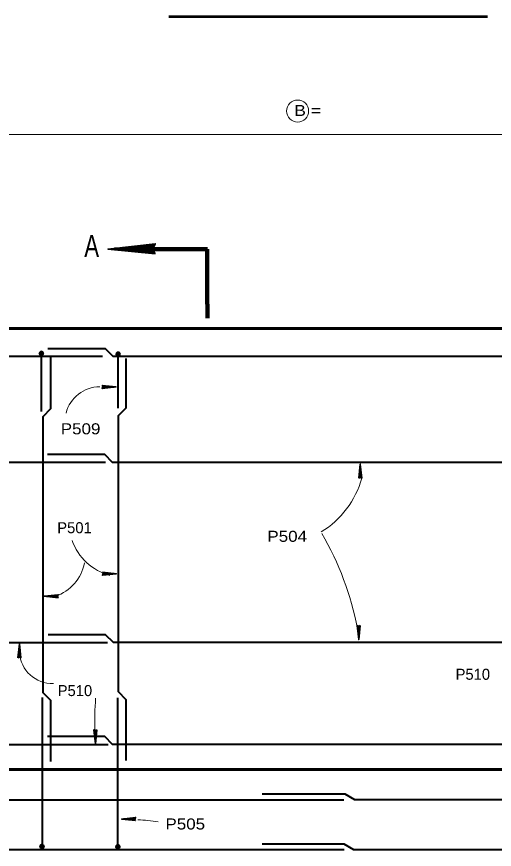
# Model space of a CAD drawing. Extents: x 14.14 to 17.34, y -1.61 to 0.38.
# Drawn here: x 14.587 to 14.948, y -1.265 to -0.636 of the extents above; entities that cross this region are included whole.
import ezdxf

# ---------------------------------------------------------------- set-up
doc = ezdxf.new("R2010")
doc.units = 0
doc.header["$LTSCALE"] = 0.0033
doc.layers.add('1', color=7, linetype='Continuous', lineweight=40)

msp = doc.modelspace()

# ---------------------------------------------------------------- linework, layer by layer
at = {"layer": '1', "lineweight": 53}
msp.add_line((14.701917, -0.636083), (14.942667, -0.636083), dxfattribs=at)
at = {"layer": '1', "lineweight": 13}
msp.add_line((14.529417, -0.725083), (15.111917, -0.725083), dxfattribs=at)
at = {"layer": '1', "lineweight": 35}
for p, q in [((14.691583, -0.81175), (14.655917, -0.81175)), ((14.690833, -0.8145), (14.66425, -0.811167)), ((14.690833, -0.8145), (14.66425, -0.81175)), ((14.690833, -0.808), (14.666083, -0.81075)), ((14.690833, -0.8085), (14.666083, -0.811167)), ((14.690833, -0.808917), (14.666083, -0.81175)), ((14.691083, -0.8095), (14.666167, -0.811917)), ((14.690833, -0.815167), (14.66425, -0.811917)), ((14.690833, -0.815167), (14.66425, -0.811917)), ((14.690833, -0.81475), (14.66425, -0.811917)), ((14.651417, -0.915917), (14.662, -0.915917)), ((14.651583, -0.916583), (14.658917, -0.915833)), ((14.651667, -0.914917), (14.6595, -0.915833)), ((14.651667, -0.914917), (14.6595, -0.915833)), ((14.651667, -0.915), (14.6595, -0.915833)), ((14.651667, -0.915083), (14.6595, -0.915917)), ((14.651667, -0.915083), (14.6595, -0.916083)), ((14.651667, -0.91675), (14.659, -0.915917)), ((14.651667, -0.916833), (14.659, -0.916083)), ((14.651667, -0.917), (14.659, -0.916167)), ((14.8465, -0.984833), (14.8465, -0.97425)), ((14.8455, -0.984583), (14.846417, -0.97675)), ((14.8455, -0.984583), (14.846417, -0.97675)), ((14.845583, -0.984583), (14.846417, -0.97675)), ((14.845667, -0.984583), (14.8465, -0.97675)), ((14.845667, -0.984583), (14.846667, -0.97675)), ((14.847167, -0.984667), (14.846417, -0.977333)), ((14.847333, -0.984583), (14.8465, -0.97725)), ((14.847417, -0.984583), (14.846667, -0.97725)), ((14.847583, -0.984583), (14.84675, -0.97725)), ((14.65175, -1.057083), (14.662333, -1.057083)), ((14.651917, -1.05775), (14.65925, -1.057)), ((14.652, -1.056083), (14.659833, -1.057)), ((14.652, -1.056083), (14.659833, -1.057)), ((14.652, -1.056167), (14.659833, -1.057)), ((14.652, -1.05625), (14.659833, -1.057083)), ((14.652, -1.05625), (14.659833, -1.05725)), ((14.652, -1.057917), (14.659333, -1.057083)), ((14.652, -1.058), (14.659333, -1.05725)), ((14.652, -1.058167), (14.659333, -1.057333)), ((14.618333, -1.074167), (14.60775, -1.074167)), ((14.618083, -1.075), (14.61025, -1.074)), ((14.618083, -1.075), (14.61025, -1.074167)), ((14.618083, -1.075167), (14.61025, -1.07425)), ((14.618083, -1.075167), (14.61025, -1.07425)), ((14.618083, -1.075083), (14.61025, -1.07425)), ((14.618083, -1.073083), (14.61075, -1.073917)), ((14.618083, -1.07325), (14.61075, -1.074)), ((14.618083, -1.073333), (14.61075, -1.074167)), ((14.618167, -1.0735), (14.610833, -1.07425)), ((14.84425, -1.096583), (14.845083, -1.103917)), ((14.844417, -1.096583), (14.845167, -1.103917)), ((14.8445, -1.096583), (14.845333, -1.103917)), ((14.844667, -1.0965), (14.845417, -1.103833)), ((14.846167, -1.096583), (14.845167, -1.104417)), ((14.845333, -1.096333), (14.845333, -1.106917)), ((14.846167, -1.096583), (14.845333, -1.104417)), ((14.846333, -1.096583), (14.845417, -1.104417)), ((14.846333, -1.096583), (14.845417, -1.104417)), ((14.84625, -1.096583), (14.845417, -1.104417)), ((14.588, -1.120417), (14.588917, -1.112583)), ((14.588, -1.120417), (14.588917, -1.112583)), ((14.588083, -1.120417), (14.588917, -1.112583)), ((14.588167, -1.120417), (14.589, -1.112583)), ((14.588167, -1.120417), (14.589167, -1.112583)), ((14.589667, -1.1205), (14.588917, -1.113167)), ((14.589, -1.120667), (14.589, -1.110083)), ((14.589833, -1.120417), (14.589, -1.113083)), ((14.589917, -1.120417), (14.589167, -1.113083)), ((14.590083, -1.120417), (14.58925, -1.113083)), ((14.645333, -1.175333), (14.646167, -1.182667)), ((14.6455, -1.175333), (14.64625, -1.182667)), ((14.645583, -1.175333), (14.646417, -1.182667)), ((14.64575, -1.17525), (14.6465, -1.182583)), ((14.64725, -1.175333), (14.64625, -1.183167)), ((14.646417, -1.175083), (14.646417, -1.185667)), ((14.64725, -1.175333), (14.646417, -1.183167)), ((14.647417, -1.175333), (14.6465, -1.183167)), ((14.647417, -1.175333), (14.6465, -1.183167)), ((14.647333, -1.175333), (14.6465, -1.183167)), ((14.67675, -1.2425), (14.666167, -1.2425)), ((14.6765, -1.243333), (14.668667, -1.242333)), ((14.6765, -1.243333), (14.668667, -1.2425)), ((14.6765, -1.2435), (14.668667, -1.242583)), ((14.6765, -1.2435), (14.668667, -1.242583)), ((14.6765, -1.243417), (14.668667, -1.242583)), ((14.6765, -1.241417), (14.669167, -1.24225)), ((14.6765, -1.241583), (14.669167, -1.242333)), ((14.6765, -1.241667), (14.669167, -1.2425)), ((14.676583, -1.241833), (14.66925, -1.242583))]:
    msp.add_line(p, q, dxfattribs=at)
at = {"layer": '1', "lineweight": 90}
for p, q in [((14.689417, -0.811833), (14.731083, -0.811833)), ((14.730917, -0.81175), (14.730917, -0.853417)), ((14.731083, -0.8535), (14.731083, -0.864))]:
    msp.add_line(p, q, dxfattribs=at)
at = {"layer": '1', "lineweight": 60}
for p, q in [((14.52925, -0.87175), (14.80725, -0.87175)), ((14.7725, -0.87175), (15.112583, -0.87175))]:
    msp.add_line(p, q, dxfattribs=at)
at = {"layer": '1'}
for p, q in [((14.547333, -0.89275), (14.65175, -0.89275)), ((14.604667, -0.891333), (14.605, -0.889417)), ((14.604833, -0.891417), (14.605167, -0.889417)), ((14.604833, -0.890417), (14.606333, -0.8905)), ((14.604833, -0.8905), (14.606333, -0.890583)), ((14.604833, -0.890583), (14.606333, -0.890667)), ((14.604833, -0.890667), (14.606333, -0.89075)), ((14.604833, -0.89075), (14.606333, -0.890833)), ((14.604833, -0.890833), (14.606333, -0.890917)), ((14.604833, -0.890917), (14.606333, -0.891)), ((14.604833, -0.891083), (14.606333, -0.891167)), ((14.604833, -0.891167), (14.606333, -0.89125)), ((14.604833, -0.89125), (14.606333, -0.891333)), ((14.604833, -0.891333), (14.606333, -0.891417)), ((14.604833, -0.891417), (14.606333, -0.8915)), ((14.604917, -0.889333), (14.606417, -0.889417)), ((14.604917, -0.891417), (14.60525, -0.889417)), ((14.604917, -0.8895), (14.606417, -0.889583)), ((14.604917, -0.889583), (14.606417, -0.889667)), ((14.604917, -0.889667), (14.606417, -0.88975)), ((14.604917, -0.88975), (14.606417, -0.889833)), ((14.604917, -0.889833), (14.606417, -0.889917)), ((14.604917, -0.889917), (14.606417, -0.89)), ((14.604917, -0.89), (14.606417, -0.890083)), ((14.604917, -0.89), (14.606417, -0.890083)), ((14.604917, -0.890083), (14.606417, -0.89025)), ((14.604917, -0.89025), (14.606417, -0.890417)), ((14.605, -0.891417), (14.605417, -0.889417)), ((14.605083, -0.891417), (14.6055, -0.889417)), ((14.60525, -0.891417), (14.605583, -0.8895)), ((14.605333, -0.8915), (14.605667, -0.8895)), ((14.605417, -0.8915), (14.605833, -0.8895)), ((14.6055, -0.8915), (14.605917, -0.889583)), ((14.6055, -0.89275), (14.6055, -0.934417)), ((14.605583, -0.8915), (14.606, -0.889583)), ((14.60575, -0.891583), (14.606167, -0.889583)), ((14.606, -0.891583), (14.606333, -0.889583)), ((14.606083, -0.891583), (14.606417, -0.889667)), ((14.606167, -0.891583), (14.6065, -0.889667)), ((14.60625, -0.891667), (14.606583, -0.889667)), ((14.662583, -0.891917), (14.662917, -0.89)), ((14.66275, -0.892), (14.663083, -0.89)), ((14.66275, -0.891), (14.66425, -0.891083)), ((14.66275, -0.891083), (14.66425, -0.891167)), ((14.66275, -0.891167), (14.66425, -0.89125)), ((14.66275, -0.89125), (14.66425, -0.891333)), ((14.66275, -0.891333), (14.66425, -0.891417)), ((14.66275, -0.891417), (14.66425, -0.8915)), ((14.66275, -0.8915), (14.66425, -0.891583)), ((14.66275, -0.891667), (14.66425, -0.89175)), ((14.66275, -0.89175), (14.66425, -0.891833)), ((14.66275, -0.891833), (14.66425, -0.891917)), ((14.66275, -0.891917), (14.66425, -0.892)), ((14.66275, -0.892), (14.66425, -0.892083)), ((14.662833, -0.889917), (14.664333, -0.89)), ((14.662833, -0.892), (14.663167, -0.89)), ((14.662833, -0.890083), (14.664333, -0.890167)), ((14.662833, -0.890167), (14.664333, -0.89025)), ((14.662833, -0.89025), (14.664333, -0.890333)), ((14.662833, -0.890333), (14.664333, -0.890417)), ((14.662833, -0.890417), (14.664333, -0.8905)), ((14.662833, -0.8905), (14.664333, -0.890583)), ((14.662833, -0.890583), (14.664333, -0.890667)), ((14.662833, -0.890583), (14.664333, -0.890667)), ((14.662833, -0.890667), (14.664333, -0.890833)), ((14.662833, -0.890833), (14.664333, -0.891)), ((14.662917, -0.892), (14.663333, -0.89)), ((14.663, -0.892), (14.663417, -0.89)), ((14.663167, -0.892), (14.6635, -0.890083)), ((14.66325, -0.892083), (14.663583, -0.890083)), ((14.663333, -0.892083), (14.66375, -0.890083)), ((14.663333, -0.89125), (14.663333, -0.932)), ((14.663417, -0.892083), (14.663833, -0.890167)), ((14.6635, -0.892083), (14.663917, -0.890167)), ((14.663667, -0.892167), (14.664083, -0.890167)), ((14.663917, -0.892167), (14.66425, -0.890167)), ((14.664, -0.892167), (14.664333, -0.89025)), ((14.664083, -0.892167), (14.664417, -0.89025)), ((14.664167, -0.89225), (14.6645, -0.89025)), ((14.547917, -0.972833), (14.654083, -0.972833)), ((14.548083, -1.109167), (14.655417, -1.109167)), ((14.606083, -1.150583), (14.606083, -1.263583)), ((14.663167, -1.150833), (14.663167, -1.263833)), ((14.549167, -1.186167), (14.656, -1.186167)), ((14.605417, -1.262083), (14.605083, -1.264083)), ((14.6055, -1.262167), (14.605167, -1.264083)), ((14.605583, -1.262167), (14.60525, -1.264083)), ((14.60675, -1.2635), (14.60525, -1.263333)), ((14.60675, -1.263667), (14.60525, -1.2635)), ((14.60675, -1.26375), (14.60525, -1.263667)), ((14.60675, -1.26375), (14.60525, -1.263667)), ((14.60675, -1.263833), (14.60525, -1.26375)), ((14.60675, -1.263917), (14.60525, -1.263833)), ((14.60675, -1.264), (14.60525, -1.263917)), ((14.60675, -1.264083), (14.60525, -1.264)), ((14.60675, -1.264167), (14.60525, -1.264083)), ((14.60675, -1.26425), (14.60525, -1.264167)), ((14.60675, -1.264417), (14.60525, -1.264333)), ((14.605667, -1.262167), (14.605333, -1.264167)), ((14.606833, -1.262333), (14.605333, -1.26225)), ((14.606833, -1.262417), (14.605333, -1.262333)), ((14.606833, -1.2625), (14.605333, -1.262417)), ((14.606833, -1.262583), (14.605333, -1.2625)), ((14.606833, -1.262667), (14.605333, -1.262583)), ((14.606833, -1.262833), (14.605333, -1.26275)), ((14.606833, -1.262917), (14.605333, -1.262833)), ((14.606833, -1.263), (14.605333, -1.262917)), ((14.606833, -1.263083), (14.605333, -1.263)), ((14.606833, -1.263167), (14.605333, -1.263083)), ((14.606833, -1.26325), (14.605333, -1.263167)), ((14.606833, -1.263333), (14.605333, -1.26325)), ((14.605917, -1.262167), (14.6055, -1.264167)), ((14.606083, -1.26225), (14.605667, -1.264167)), ((14.606167, -1.26225), (14.60575, -1.264167)), ((14.60625, -1.26225), (14.605833, -1.26425)), ((14.606333, -1.26225), (14.606, -1.26425)), ((14.606417, -1.262333), (14.606083, -1.26425)), ((14.606583, -1.262333), (14.606167, -1.264333)), ((14.606667, -1.262333), (14.60625, -1.264333)), ((14.60675, -1.262333), (14.606417, -1.264333)), ((14.606833, -1.262333), (14.6065, -1.264333)), ((14.607, -1.262417), (14.606667, -1.264333)), ((14.66275, -1.26225), (14.662417, -1.26425)), ((14.662833, -1.262333), (14.6625, -1.26425)), ((14.662917, -1.262333), (14.662583, -1.26425)), ((14.664083, -1.263667), (14.662583, -1.2635)), ((14.664083, -1.263833), (14.662583, -1.263667)), ((14.664083, -1.263917), (14.662583, -1.263833)), ((14.664083, -1.263917), (14.662583, -1.263833)), ((14.664083, -1.264), (14.662583, -1.263917)), ((14.664083, -1.264083), (14.662583, -1.264)), ((14.664083, -1.264167), (14.662583, -1.264083)), ((14.664083, -1.26425), (14.662583, -1.264167)), ((14.664083, -1.264333), (14.662583, -1.26425)), ((14.664083, -1.264417), (14.662583, -1.264333)), ((14.664083, -1.264583), (14.662583, -1.2645)), ((14.663, -1.262333), (14.662667, -1.264333)), ((14.664167, -1.2625), (14.662667, -1.262417)), ((14.664167, -1.262583), (14.662667, -1.2625)), ((14.664167, -1.262667), (14.662667, -1.262583)), ((14.664167, -1.26275), (14.662667, -1.262667)), ((14.664167, -1.262833), (14.662667, -1.26275)), ((14.664167, -1.263), (14.662667, -1.262917)), ((14.664167, -1.263083), (14.662667, -1.263)), ((14.664167, -1.263167), (14.662667, -1.263083)), ((14.664167, -1.26325), (14.662667, -1.263167)), ((14.664167, -1.263333), (14.662667, -1.26325)), ((14.664167, -1.263417), (14.662667, -1.263333)), ((14.664167, -1.2635), (14.662667, -1.263417)), ((14.66325, -1.262333), (14.662833, -1.264333)), ((14.663417, -1.262417), (14.663, -1.264333)), ((14.6635, -1.262417), (14.663083, -1.264333)), ((14.663583, -1.262417), (14.663167, -1.264417)), ((14.663667, -1.262417), (14.663333, -1.264417)), ((14.66375, -1.2625), (14.663417, -1.264417)), ((14.663917, -1.2625), (14.6635, -1.2645)), ((14.664, -1.2625), (14.663583, -1.2645)), ((14.664083, -1.2625), (14.66375, -1.2645)), ((14.664167, -1.2625), (14.663833, -1.2645)), ((14.664333, -1.262583), (14.664, -1.2645))]:
    msp.add_line(p, q, dxfattribs=at)
at = {"layer": '1', "lineweight": 35}
for points in [[(14.691583, -0.81525), (14.655917, -0.81175), (14.691583, -0.80775), (14.689667, -0.81175)], [(14.689167, -0.811917), (14.673333, -0.81225), (14.673333, -0.811917), (14.676333, -0.811917), (14.689167, -0.81225), (14.678917, -0.8125), (14.689667, -0.812917), (14.681917, -0.813), (14.689667, -0.813417), (14.677833, -0.8125), (14.662, -0.811917), (14.665083, -0.811167), (14.660917, -0.811167), (14.689167, -0.811167), (14.680833, -0.810667), (14.689667, -0.810667), (14.671667, -0.811917), (14.689667, -0.809667)], [(14.651417, -0.914833), (14.662, -0.915917), (14.651417, -0.917083), (14.652, -0.915917)], [(14.652167, -0.915833), (14.656833, -0.91575), (14.656833, -0.915833), (14.655917, -0.915833), (14.652167, -0.91575), (14.655167, -0.915667), (14.652, -0.915583), (14.65425, -0.9155), (14.652, -0.915417), (14.6555, -0.915667), (14.660167, -0.915833), (14.65925, -0.916083), (14.6605, -0.916083), (14.652167, -0.916083), (14.654583, -0.91625), (14.652, -0.91625), (14.657333, -0.915833), (14.652, -0.9165)], [(14.845417, -0.984833), (14.8465, -0.97425), (14.847667, -0.984833), (14.8465, -0.98425)], [(14.846417, -0.984083), (14.846333, -0.979417), (14.846417, -0.979417), (14.846417, -0.980333), (14.846333, -0.984083), (14.84625, -0.981083), (14.846167, -0.98425), (14.846083, -0.982), (14.846, -0.98425), (14.84625, -0.98075), (14.846417, -0.976083), (14.846667, -0.977), (14.846667, -0.97575), (14.846667, -0.984083), (14.846833, -0.981667), (14.846833, -0.98425), (14.846417, -0.978917), (14.847083, -0.98425)], [(14.65175, -1.056), (14.662333, -1.057083), (14.65175, -1.05825), (14.652333, -1.057083)], [(14.6525, -1.057), (14.657167, -1.056917), (14.657167, -1.057), (14.65625, -1.057), (14.6525, -1.056917), (14.6555, -1.056833), (14.652333, -1.05675), (14.654583, -1.056667), (14.652333, -1.056583), (14.655833, -1.056833), (14.6605, -1.057), (14.659583, -1.05725), (14.660833, -1.05725), (14.6525, -1.05725), (14.654917, -1.057417), (14.652333, -1.057417), (14.657667, -1.057), (14.652333, -1.057667)], [(14.618333, -1.07525), (14.60775, -1.074167), (14.618333, -1.073), (14.61775, -1.074167)], [(14.617583, -1.07425), (14.612917, -1.074333), (14.612917, -1.07425), (14.613833, -1.07425), (14.617583, -1.074333), (14.614583, -1.074417), (14.61775, -1.0745), (14.6155, -1.074583), (14.61775, -1.074667), (14.61425, -1.074417), (14.609583, -1.07425), (14.6105, -1.074), (14.60925, -1.074), (14.617583, -1.074), (14.615167, -1.073833), (14.61775, -1.073833), (14.612417, -1.07425), (14.61775, -1.073583)], [(14.846417, -1.096333), (14.845333, -1.106917), (14.844167, -1.096333), (14.845333, -1.096917)], [(14.845417, -1.097083), (14.8455, -1.10175), (14.845417, -1.10175), (14.845417, -1.100833), (14.8455, -1.097083), (14.845583, -1.100083), (14.845667, -1.096917), (14.84575, -1.099167), (14.845833, -1.096917), (14.845583, -1.100417), (14.845417, -1.105083), (14.845167, -1.104167), (14.845167, -1.105417), (14.845167, -1.097083), (14.845, -1.0995), (14.845, -1.096917), (14.845417, -1.10225), (14.84475, -1.096917)], [(14.587917, -1.120667), (14.589, -1.110083), (14.590167, -1.120667), (14.589, -1.120083)], [(14.588917, -1.119917), (14.588833, -1.11525), (14.588917, -1.11525), (14.588917, -1.116167), (14.588833, -1.119917), (14.58875, -1.116917), (14.588667, -1.120083), (14.588583, -1.117833), (14.5885, -1.120083), (14.58875, -1.116583), (14.588917, -1.111917), (14.589167, -1.112833), (14.589167, -1.111583), (14.589167, -1.119917), (14.589333, -1.1175), (14.589333, -1.120083), (14.588917, -1.11475), (14.589583, -1.120083)], [(14.6475, -1.175083), (14.646417, -1.185667), (14.64525, -1.175083), (14.646417, -1.175667)], [(14.6465, -1.175833), (14.646583, -1.1805), (14.6465, -1.1805), (14.6465, -1.179583), (14.646583, -1.175833), (14.646667, -1.178833), (14.64675, -1.175667), (14.646833, -1.177917), (14.646917, -1.175667), (14.646667, -1.179167), (14.6465, -1.183833), (14.64625, -1.182917), (14.64625, -1.184167), (14.64625, -1.175833), (14.646083, -1.17825), (14.646083, -1.175667), (14.6465, -1.181), (14.645833, -1.175667)], [(14.67675, -1.243583), (14.666167, -1.2425), (14.67675, -1.241333), (14.676167, -1.2425)], [(14.676, -1.242583), (14.671333, -1.242667), (14.671333, -1.242583), (14.67225, -1.242583), (14.676, -1.242667), (14.673, -1.24275), (14.676167, -1.242833), (14.673917, -1.242917), (14.676167, -1.243), (14.672667, -1.24275), (14.668, -1.242583), (14.668917, -1.242333), (14.667667, -1.242333), (14.676, -1.242333), (14.673583, -1.242167), (14.676167, -1.242167), (14.670833, -1.242583), (14.676167, -1.241917)]]:
    msp.add_lwpolyline(points, close=True, dxfattribs=at)
for points in [[(14.689167, -0.811917), (14.690417, -0.8145), (14.689667, -0.813667), (14.689167, -0.8125), (14.688167, -0.812917), (14.688833, -0.814), (14.689333, -0.811417), (14.689917, -0.809667), (14.690833, -0.808417)], [(14.652167, -0.915833), (14.65175, -0.915083), (14.652, -0.915333), (14.652167, -0.915667), (14.652417, -0.915583), (14.65225, -0.91525), (14.652083, -0.916), (14.651917, -0.9165), (14.651667, -0.916917)], [(14.846417, -0.984083), (14.845667, -0.9845), (14.845917, -0.98425), (14.84625, -0.984083), (14.846167, -0.983833), (14.845833, -0.984), (14.846583, -0.984167), (14.847083, -0.984333), (14.8475, -0.984583)], [(14.6525, -1.057), (14.652083, -1.05625), (14.652333, -1.0565), (14.6525, -1.056833), (14.65275, -1.05675), (14.652583, -1.056417), (14.652417, -1.057167), (14.65225, -1.057667), (14.652, -1.058083)], [(14.617583, -1.07425), (14.618, -1.075), (14.61775, -1.07475), (14.617583, -1.074417), (14.617333, -1.0745), (14.6175, -1.074833), (14.617667, -1.074083), (14.617833, -1.073583), (14.618083, -1.073167)], [(14.845417, -1.097083), (14.846167, -1.096667), (14.845917, -1.096917), (14.845583, -1.097083), (14.845667, -1.097333), (14.846, -1.097167), (14.84525, -1.097), (14.84475, -1.096833), (14.844333, -1.096583)], [(14.588917, -1.119917), (14.588167, -1.120333), (14.588417, -1.120083), (14.58875, -1.119917), (14.588667, -1.119667), (14.588333, -1.119833), (14.589083, -1.12), (14.589583, -1.120167), (14.59, -1.120417)], [(14.6465, -1.175833), (14.64725, -1.175417), (14.647, -1.175667), (14.646667, -1.175833), (14.64675, -1.176083), (14.647083, -1.175917), (14.646333, -1.17575), (14.645833, -1.175583), (14.645417, -1.175333)], [(14.676, -1.242583), (14.676417, -1.243333), (14.676167, -1.243083), (14.676, -1.24275), (14.67575, -1.242833), (14.675917, -1.243167), (14.676083, -1.242417), (14.67625, -1.241917), (14.6765, -1.2415)]]:
    msp.add_lwpolyline(points, dxfattribs=at)
at = {"layer": '1'}
for points in [[(15.019083, -0.887083), (14.975417, -0.887083), (14.9695, -0.893), (14.75475, -0.893), (14.659833, -0.893), (14.653917, -0.887083), (14.610583, -0.887083)], [(14.605667, -0.891833), (14.605333, -0.88925), (14.604833, -0.891583), (14.605917, -0.88925), (14.606333, -0.891667), (14.606667, -0.889667), (14.604583, -0.889667), (14.606917, -0.890583), (14.604333, -0.890333), (14.606667, -0.891333), (14.604333, -0.891), (14.606917, -0.890167), (14.605167, -0.89175), (14.605, -0.889333), (14.606833, -0.891), (14.604417, -0.889917), (14.604833, -0.891583), (14.606333, -0.891667), (14.606917, -0.890583), (14.606667, -0.889667), (14.605917, -0.88925), (14.605, -0.889333), (14.604417, -0.889917), (14.6055, -0.890583), (14.606417, -0.889417), (14.606667, -0.891333), (14.6055, -0.890583), (14.605, -0.891667), (14.604333, -0.890667), (14.605417, -0.890583), (14.606667, -0.88975), (14.605417, -0.89175), (14.605083, -0.890417), (14.604583, -0.889667)], [(14.612583, -0.893167), (14.612583, -0.9325), (14.606667, -0.938417), (14.606667, -1.14675), (14.612583, -1.152667), (14.612583, -1.198917)], [(14.663583, -0.892417), (14.66325, -0.889833), (14.66275, -0.892167), (14.663833, -0.889833), (14.66425, -0.89225), (14.664583, -0.89025), (14.6625, -0.89025), (14.664833, -0.891167), (14.66225, -0.890917), (14.664583, -0.891917), (14.66225, -0.891583), (14.664833, -0.89075), (14.663083, -0.892333), (14.662917, -0.889917), (14.66475, -0.891583), (14.662333, -0.8905), (14.66275, -0.892167), (14.66425, -0.89225), (14.664833, -0.891167), (14.664583, -0.89025), (14.663833, -0.889833), (14.662917, -0.889917), (14.662333, -0.8905), (14.663417, -0.891167), (14.664333, -0.89), (14.664583, -0.891917), (14.663417, -0.891167), (14.662917, -0.89225), (14.66225, -0.89125), (14.663333, -0.891167), (14.664583, -0.890333), (14.663333, -0.892333), (14.663, -0.891), (14.6625, -0.89025)], [(14.669417, -0.894333), (14.669417, -0.931917), (14.6635, -0.937833), (14.6635, -1.146167), (14.669417, -1.152083), (14.669417, -1.198333)], [(15.018667, -0.967083), (14.975, -0.967083), (14.969083, -0.973), (14.754333, -0.973), (14.659417, -0.973), (14.6535, -0.967083), (14.610167, -0.967083)], [(15.01925, -1.10325), (14.975583, -1.10325), (14.969667, -1.109167), (14.754917, -1.109167), (14.66, -1.109167), (14.654083, -1.10325), (14.61075, -1.10325)], [(15.018667, -1.180167), (14.975, -1.180167), (14.969083, -1.186083), (14.754333, -1.186083), (14.659417, -1.186083), (14.6535, -1.180167), (14.610167, -1.180167)], [(14.772417, -1.2235), (14.83475, -1.2235), (14.842, -1.227667), (15.177417, -1.227667)], [(14.464333, -1.228), (14.772417, -1.228), (14.834167, -1.228)], [(14.606, -1.261917), (14.606333, -1.2645), (14.606833, -1.262167), (14.60575, -1.2645), (14.605333, -1.262083), (14.605, -1.264083), (14.607083, -1.264083), (14.60475, -1.263167), (14.607333, -1.263417), (14.605, -1.262417), (14.607333, -1.26275), (14.60475, -1.263583), (14.6065, -1.262), (14.606667, -1.264417), (14.604833, -1.26275), (14.60725, -1.263833), (14.606833, -1.262167), (14.605333, -1.262083), (14.60475, -1.263167), (14.605, -1.264083), (14.60575, -1.2645), (14.606667, -1.264417), (14.60725, -1.263833), (14.606167, -1.263167), (14.60525, -1.264333), (14.605, -1.262417), (14.606167, -1.263167), (14.606667, -1.262083), (14.607333, -1.263083), (14.60625, -1.263167), (14.605, -1.264), (14.60625, -1.262), (14.606583, -1.263333), (14.607083, -1.264083)], [(14.663333, -1.262083), (14.663667, -1.264667), (14.664167, -1.262333), (14.663083, -1.264667), (14.662667, -1.26225), (14.662333, -1.26425), (14.664417, -1.26425), (14.662083, -1.263333), (14.664667, -1.263583), (14.662333, -1.262583), (14.664667, -1.262917), (14.662083, -1.26375), (14.663833, -1.262167), (14.664, -1.264583), (14.662167, -1.262917), (14.664583, -1.264), (14.664167, -1.262333), (14.662667, -1.26225), (14.662083, -1.263333), (14.662333, -1.26425), (14.663083, -1.264667), (14.664, -1.264583), (14.664583, -1.264), (14.6635, -1.263333), (14.662583, -1.2645), (14.662333, -1.262583), (14.6635, -1.263333), (14.664, -1.26225), (14.664667, -1.26325), (14.663583, -1.263333), (14.662333, -1.264167), (14.663583, -1.262167), (14.663917, -1.2635), (14.664417, -1.26425)], [(14.7725, -1.26125), (14.834083, -1.26125), (14.841333, -1.265417), (15.17825, -1.265417)], [(14.4635, -1.265417), (14.7725, -1.265417), (14.834417, -1.265417)]]:
    msp.add_lwpolyline(points, dxfattribs=at)
at = {"layer": '1', "lineweight": 60}
msp.add_lwpolyline([(14.52925, -1.205083), (14.772417, -1.205083), (15.112583, -1.205083)], dxfattribs=at)
at = {"layer": '1', "lineweight": 13}
msp.add_circle((14.799167, -0.707417), 0.008333, dxfattribs=at)
at = {"layer": '1'}
for centre in [(14.605617, -0.8905), (14.663533, -0.891083), (14.60605, -1.26325), (14.663383, -1.263417)]:
    msp.add_circle(centre, 0.00132, dxfattribs=at)
at = {"layer": '1', "lineweight": 13}
for centre, radius, start, end in [((14.649762, -0.942132), 0.026298, 90.20866, 165.95631), ((14.780561, -0.966263), 0.069548, 301.5972, 344.51287), ((14.668014, -1.018071), 0.041634, 199.42455, 255.25359), ((14.620506, -1.141411), 0.227904, 10.8527, 30.23025), ((14.605694, -1.042869), 0.032964, 288.49999, 349.28048), ((14.613945, -1.115102), 0.024994, 183.58816, 271.84601), ((14.857149, -1.168375), 0.211261, 175.35045, 181.86489), ((14.674332, -1.365493), 0.12248, 80.89644, 88.05006)]:
    msp.add_arc(centre, radius, start, end, dxfattribs=at)

# ---------------------------------------------------------------- texts
at = {"layer": '1'}
for s, height, width, p in [('B =      ', 0.008334, 1.2, (14.7965, -0.711167)), ('A', 0.01667, 0.75, (14.638, -0.817667)), ('P509', 0.008334, 1.15, (14.62025, -0.95175)), ('P504', 0.008334, 1.15, (14.776333, -1.033)), ('P505', 0.008334, 1.15, (14.699333, -1.250417))]:
    msp.add_text(s, height=height, dxfattribs=dict(at, width=width)).set_placement(p)
for s, p in [('P501', (14.617583, -1.0265)), ('P510', (14.9185, -1.13725)), ('P510', (14.617917, -1.149583))]:
    msp.add_text(s, height=0.008334, dxfattribs=at).set_placement(p)

doc.saveas('drawing.dxf')
